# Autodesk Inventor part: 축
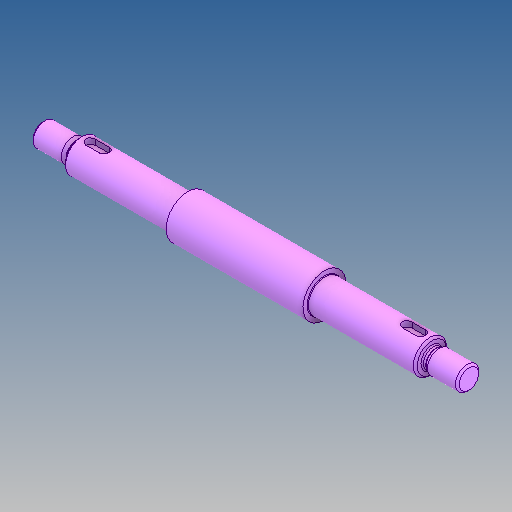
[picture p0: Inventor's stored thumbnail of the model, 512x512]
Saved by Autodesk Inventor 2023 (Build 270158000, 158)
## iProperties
Created: 2025-03
Part Number: 축
Material: 강철, 탄소
Document SubType Name: Modeling
Designer: Admin
Density: 7.85 g/cm^3
Appearance: 기본값
Author: jhkim
Sending System: Autodesk Inventor 2025
Preprocessor: ST-DEVELOPER v20
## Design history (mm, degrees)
node "축1"
node "솔리드2"
node "솔리드1"
